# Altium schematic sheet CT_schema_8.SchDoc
size 277 x 170 mm
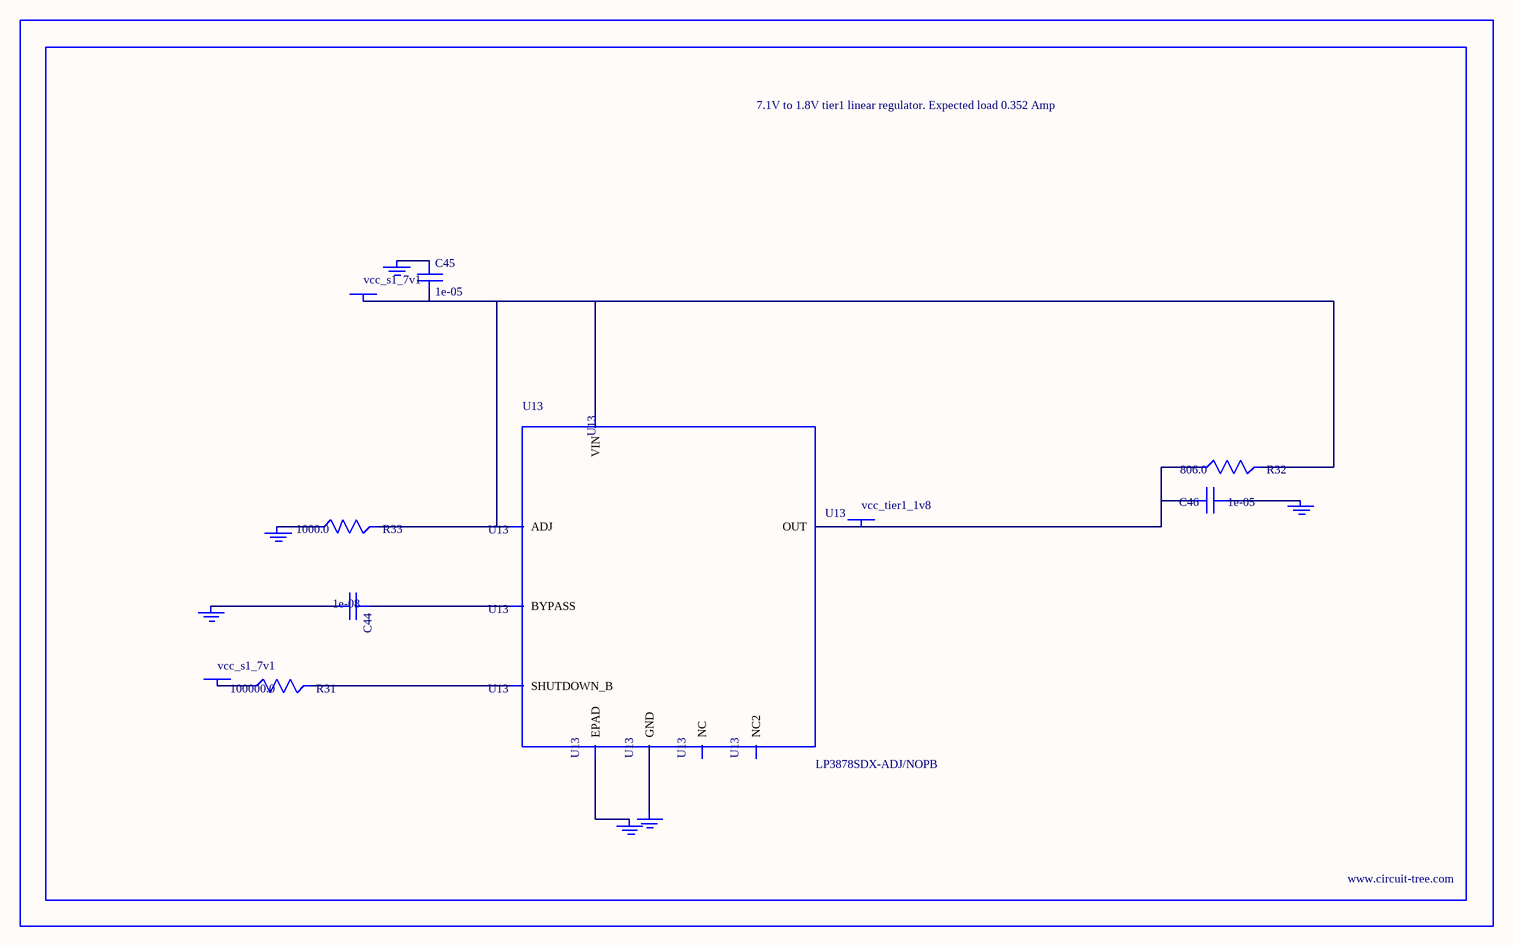
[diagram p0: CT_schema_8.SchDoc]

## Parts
BORDER7  (no value)
C44  1e-08  [C0402]
C45  1e-05  [C1206]
C46  1e-05  [C0805]
GND_INSTANCE_7_0  (no value)
GND_INSTANCE_7_1  (no value)
GND_INSTANCE_7_2  (no value)
GND_INSTANCE_7_3  (no value)
GND_INSTANCE_7_4  (no value)
GND_INSTANCE_7_5  (no value)
POWER_INSTANCE_7_0  vcc_s1_7v1
POWER_INSTANCE_7_1  vcc_s1_7v1
POWER_INSTANCE_7_2  vcc_tier1_1v8
R31  100000.0  [R0603]
R32  806.0  [R0603]
R33  1000.0  [R0603]
U13  LP3878SDX-ADJ/NOPB  [WSON-8]

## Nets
NetC44_1: C44.1 U13.1(BYPASS)
NetC44_2: C44.2 GND_INSTANCE_7_0.0(GND)
NetC45_1: C45.1 GND_INSTANCE_7_1.0(GND)
NetC45_2: C45.2 POWER_INSTANCE_7_0.0(PWR) R32.2 R33.2 U13.4(VIN) U13.6(ADJ)
NetC46_1: C46.1 GND_INSTANCE_7_2.0(GND)
NetC46_2: C46.2 POWER_INSTANCE_7_2.0(PWR) R32.1 U13.5(OUT)
NetGND_INSTANCE_7_3_0: GND_INSTANCE_7_3.0(GND) R33.1
NetGND_INSTANCE_7_4_0: GND_INSTANCE_7_4.0(GND) U13.PAD(EPAD)
NetGND_INSTANCE_7_5_0: GND_INSTANCE_7_5.0(GND) U13.3(GND)
NetPOWER_INSTANCE_7_1_0: POWER_INSTANCE_7_1.0(PWR) R31.1
NetR31_2: R31.2 U13.8(SHUTDOWN_B)

Not connected (* = marked no-connect by the designer): U13 2(NC) 7(NC2)

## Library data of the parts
BORDER7 = BORDER_PAGE7
C44 = C0402C103K3RAC
C45 = C1206C106K3RACTU
C46 = GRM219R60J106ME19D
GND_INSTANCE_7_0-GND_INSTANCE_7_5 = GND
POWER_INSTANCE_7_0-POWER_INSTANCE_7_2 = PWR
R31 = RC0603JR-07100KL
R32 = ERJ-3EKF8060V
R33 = RC0603JR-071KL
